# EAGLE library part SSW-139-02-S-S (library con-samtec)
THROUGH-HOLE .025" SQ POST SOCKET Source: Samtec SSW.pdf
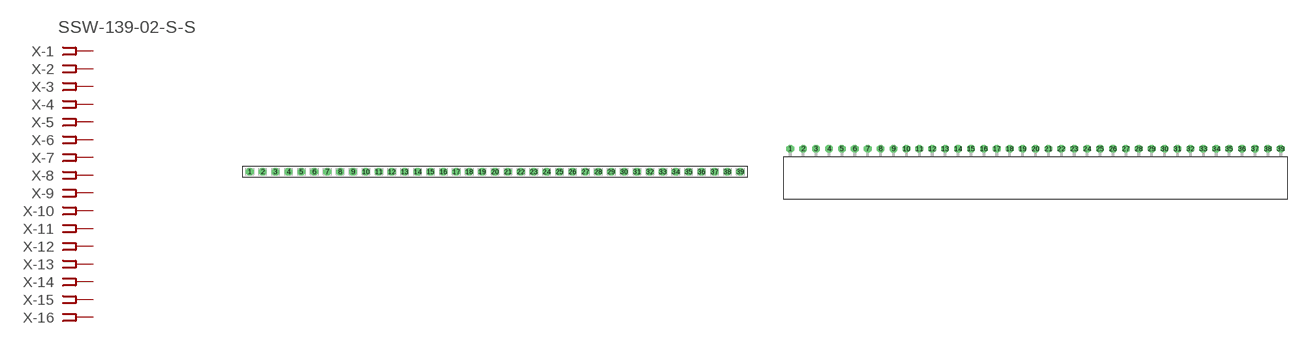
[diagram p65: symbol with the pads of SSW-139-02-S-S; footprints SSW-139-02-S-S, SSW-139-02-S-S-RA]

Designator prefix X; gates -1=FPINV -2=FPIN -3=FPIN -4=FPIN -5=FPIN -6=FPIN -7=FPIN -8=FPIN -9=FPIN -10=FPIN -11=FPIN -12=FPIN -13=FPIN -14=FPIN -15=FPIN -16=FPIN -17=FPIN -18=FPIN -19=FPIN -20=FPIN -21=FPIN -22=FPIN -23=FPIN -24=FPIN -25=FPIN -26=FPIN -27=FPIN -28=FPIN -29=FPIN -30=FPIN -31=FPIN -32=FPIN -33=FPIN -34=FPIN -35=FPIN -36=FPIN -37=FPIN -38=FPIN -39=FPIN

## SSW-139-02-S-S (OC_FARNELL: unknown; OC_NEWARK: unknown)  [SSW-139-02-S-S]
1  -1:1  pas
2  -2:1  pas
3  -3:1  pas
4  -4:1  pas
5  -5:1  pas
6  -6:1  pas
7  -7:1  pas
8  -8:1  pas
9  -9:1  pas
10  -10:1  pas
11  -11:1  pas
12  -12:1  pas
13  -13:1  pas
14  -14:1  pas
15  -15:1  pas
16  -16:1  pas
17  -17:1  pas
18  -18:1  pas
19  -19:1  pas
20  -20:1  pas
21  -21:1  pas
22  -22:1  pas
23  -23:1  pas
24  -24:1  pas
25  -25:1  pas
26  -26:1  pas
27  -27:1  pas
28  -28:1  pas
29  -29:1  pas
30  -30:1  pas
31  -31:1  pas
32  -32:1  pas
33  -33:1  pas
34  -34:1  pas
35  -35:1  pas
36  -36:1  pas
37  -37:1  pas
38  -38:1  pas
39  -39:1  pas

## SSW-139-02-S-S-RA (OC_FARNELL: unknown; OC_NEWARK: unknown)  [SSW-139-02-S-S-RA]
Pads as for SSW-139-02-S-S

## Footprint SSW-139-02-S-S (pad centres in mm)
THROUGH-HOLE .025" SQ POST SOCKET Source: Samtec SSW.pdf
drill 1 pad 1.5 octagon: 1 -48.26,0; 2 -45.72,0; 3 -43.18,0; 4 -40.64,0; 5 -38.1,0; 6 -35.56,0; 7 -33.02,0; 8 -30.48,0; 9 -27.94,0; 10 -25.4,0; 11 -22.86,0; 12 -20.32,0; 13 -17.78,0; 14 -15.24,0; 15 -12.7,0; 16 -10.16,0; 17 -7.62,0; 18 -5.08,0; 19 -2.54,0; 20 0,0; 21 2.54,0; 22 5.08,0; 23 7.62,0; 24 10.16,0; 25 12.7,0; 26 15.24,0; 27 17.78,0; 28 20.32,0; 29 22.86,0; 30 25.4,0; 31 27.94,0; 32 30.48,0; 33 33.02,0; 34 35.56,0; 35 38.1,0; 36 40.64,0; 37 43.18,0; 38 45.72,0; 39 48.26,0

## Footprint SSW-139-02-S-S-RA (pad centres in mm)
THROUGH-HOLE .025" SQ POST SOCKET Source: Samtec SSW.pdf
drill 1 pad 1.5 octagon: 1 -48.26,1.524; 2 -45.72,1.524; 3 -43.18,1.524; 4 -40.64,1.524; 5 -38.1,1.524; 6 -35.56,1.524; 7 -33.02,1.524; 8 -30.48,1.524; 9 -27.94,1.524; 10 -25.4,1.524; 11 -22.86,1.524; 12 -20.32,1.524; 13 -17.78,1.524; 14 -15.24,1.524; 15 -12.7,1.524; 16 -10.16,1.524; 17 -7.62,1.524; 18 -5.08,1.524; 19 -2.54,1.524; 20 0,1.524; 21 2.54,1.524; 22 5.08,1.524; 23 7.62,1.524; 24 10.16,1.524; 25 12.7,1.524; 26 15.24,1.524; 27 17.78,1.524; 28 20.32,1.524; 29 22.86,1.524; 30 25.4,1.524; 31 27.94,1.524; 32 30.48,1.524; 33 33.02,1.524; 34 35.56,1.524; 35 38.1,1.524; 36 40.64,1.524; 37 43.18,1.524; 38 45.72,1.524; 39 48.26,1.524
